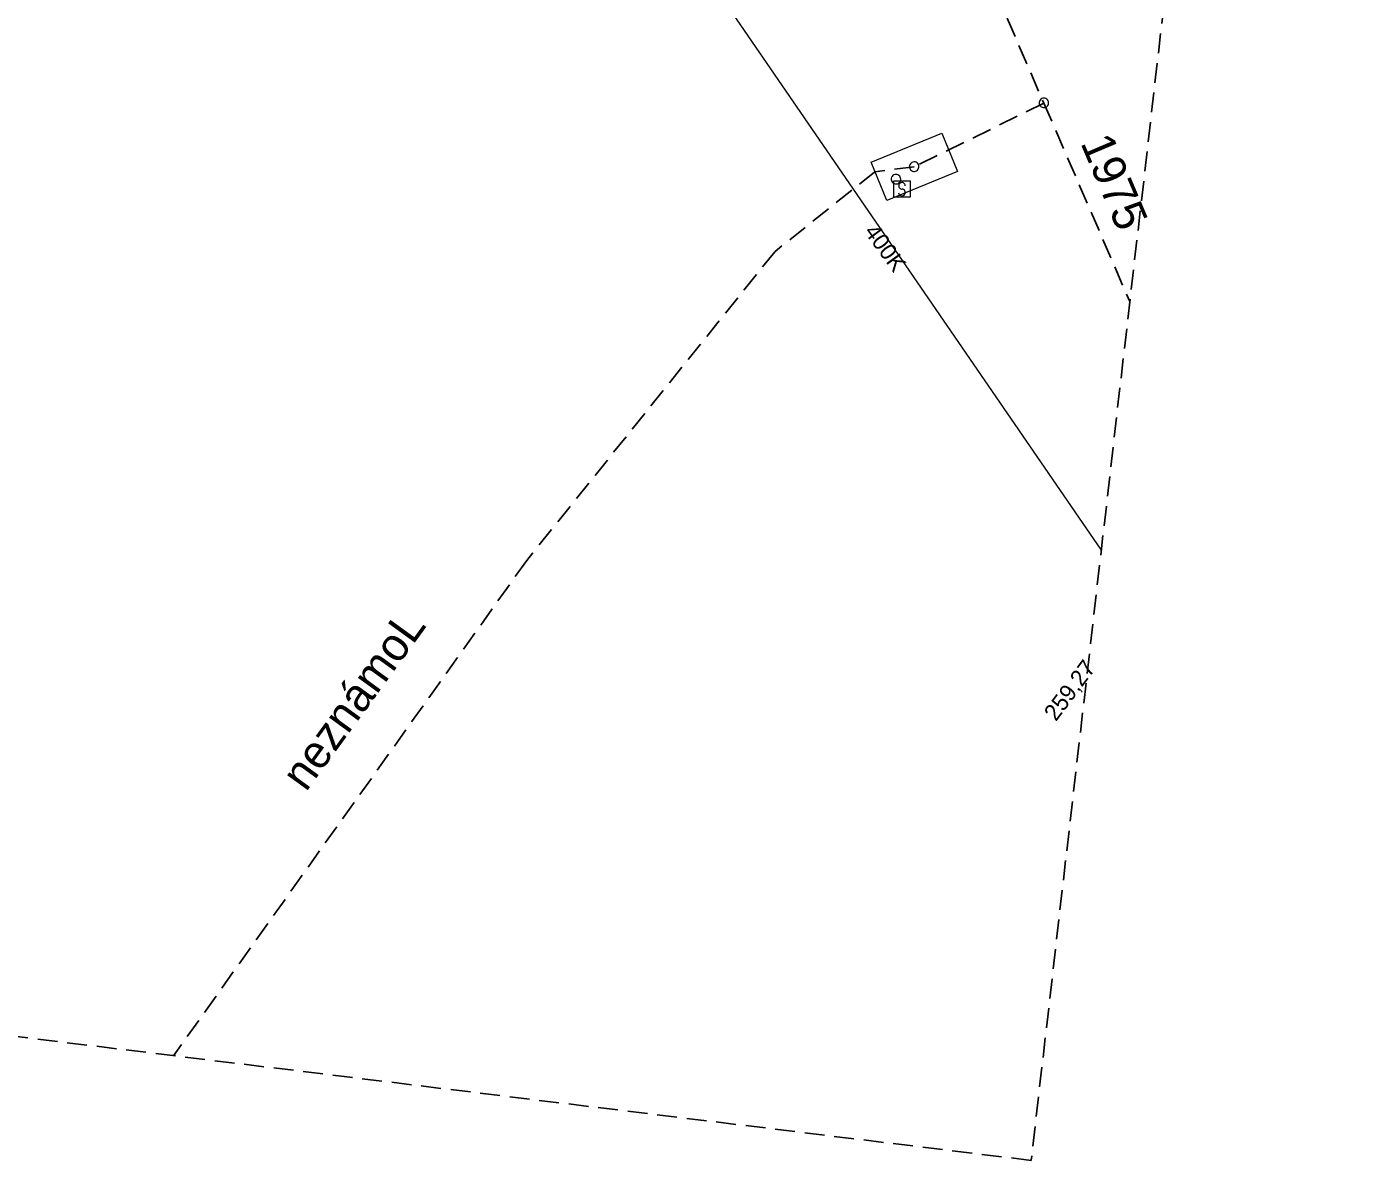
# Model space of a CAD drawing. Extents: x -743212 to -743020, y -1051380 to -1051228.
# Drawn here: x -743084.5 to -743020, y -1051380.3 to -1051325.4 of the extents above; entities that cross this region are included whole.
import ezdxf

# ---------------------------------------------------------------- set-up
doc = ezdxf.new("R2010")
doc.units = 0
doc.header["$LTSCALE"] = 0.32
doc.linetypes.add('MEDIUM_DASHED', pattern=[4.5, 3, -1.5])
for name, color, linetype, lineweight in [('1', 7, 'MEDIUM_DASHED', 25), ('20', 7, 'Continuous', 13), ('8', 7, 'Continuous', 13)]:
    doc.layers.add(name, color=color, linetype=linetype, lineweight=lineweight)

msp = doc.modelspace()

# ---------------------------------------------------------------- linework, layer by layer
at = {"layer": '1'}
msp.add_lwpolyline([(-743194.153, -1051227.724), (-743020.025, -1051242.759), (-743020.023, -1051242.759), (-743020.021, -1051242.76), (-743020.02, -1051242.761), (-743020.018, -1051242.762), (-743020.017, -1051242.764), (-743020.016, -1051242.766), (-743020.016, -1051242.768), (-743020.016, -1051242.77), (-743035.817, -1051380.315), (-743035.817, -1051380.317), (-743035.818, -1051380.318), (-743035.819, -1051380.32), (-743035.82, -1051380.321), (-743035.822, -1051380.322), (-743035.824, -1051380.323), (-743035.826, -1051380.323), (-743035.828, -1051380.323), (-743211.786, -1051358.847)], dxfattribs=at)
at = {"layer": '20'}
msp.add_line((-743053.699, -1051319.8), (-743032.423, -1051350.772), dxfattribs=at)
msp.add_line((-743053.699, -1051319.8), (-743032.423, -1051350.772), dxfattribs=at)
at = {"layer": '8', "linetype": 'MEDIUM_DASHED', "lineweight": 25}
for p, q in [((-743041.565, -1051314.439), (-743035.204, -1051329.117)), ((-743035.204, -1051329.117), (-743041.488, -1051332.205)), ((-743035.204, -1051329.117), (-743031.04, -1051338.73))]:
    msp.add_line(p, q, dxfattribs=at)
at = {"layer": '8'}
for points in [[(-743034.973, -1051329.106), (-743034.979, -1051329.054), (-743034.997, -1051329.004), (-743035.025, -1051328.96), (-743035.063, -1051328.923), (-743035.108, -1051328.896), (-743035.158, -1051328.88), (-743035.21, -1051328.875), (-743035.262, -1051328.882), (-743035.311, -1051328.901), (-743035.355, -1051328.931), (-743035.39, -1051328.97), (-743035.416, -1051329.015), (-743035.431, -1051329.066), (-743035.434, -1051329.118), (-743035.426, -1051329.17), (-743035.405, -1051329.218), (-743035.375, -1051329.261), (-743035.335, -1051329.296), (-743035.289, -1051329.32), (-743035.238, -1051329.334), (-743035.186, -1051329.336), (-743035.134, -1051329.326), (-743035.086, -1051329.304), (-743035.044, -1051329.272), (-743035.011, -1051329.232), (-743034.987, -1051329.185), (-743034.975, -1051329.134)], [(-743040.149, -1051330.58), (-743039.394, -1051332.432), (-743042.82, -1051333.83), (-743043.576, -1051331.977)], [(-743041.257, -1051332.194), (-743041.263, -1051332.142), (-743041.281, -1051332.092), (-743041.309, -1051332.048), (-743041.347, -1051332.011), (-743041.392, -1051331.984), (-743041.442, -1051331.968), (-743041.494, -1051331.963), (-743041.546, -1051331.97), (-743041.595, -1051331.989), (-743041.639, -1051332.019), (-743041.674, -1051332.058), (-743041.7, -1051332.103), (-743041.715, -1051332.154), (-743041.718, -1051332.206), (-743041.71, -1051332.258), (-743041.689, -1051332.306), (-743041.659, -1051332.349), (-743041.619, -1051332.384), (-743041.573, -1051332.408), (-743041.522, -1051332.422), (-743041.47, -1051332.424), (-743041.418, -1051332.414), (-743041.37, -1051332.392), (-743041.328, -1051332.36), (-743041.295, -1051332.32), (-743041.271, -1051332.273), (-743041.259, -1051332.222)], [(-743042.137, -1051332.8), (-743042.143, -1051332.748), (-743042.161, -1051332.698), (-743042.189, -1051332.654), (-743042.227, -1051332.617), (-743042.272, -1051332.59), (-743042.322, -1051332.574), (-743042.374, -1051332.569), (-743042.426, -1051332.576), (-743042.475, -1051332.595), (-743042.519, -1051332.625), (-743042.554, -1051332.664), (-743042.58, -1051332.709), (-743042.595, -1051332.76), (-743042.598, -1051332.812), (-743042.59, -1051332.864), (-743042.569, -1051332.912), (-743042.539, -1051332.955), (-743042.499, -1051332.99), (-743042.453, -1051333.014), (-743042.402, -1051333.028), (-743042.35, -1051333.03), (-743042.298, -1051333.02), (-743042.25, -1051332.998), (-743042.208, -1051332.966), (-743042.175, -1051332.926), (-743042.151, -1051332.879), (-743042.139, -1051332.828)], [(-743042.468, -1051332.878), (-743041.678, -1051332.878), (-743041.678, -1051333.678), (-743042.468, -1051333.678)]]:
    msp.add_lwpolyline(points, close=True, dxfattribs=at)
at = {"layer": '8', "linetype": 'MEDIUM_DASHED', "lineweight": 25}
msp.add_lwpolyline([(-743041.488, -1051332.205), (-743043.39, -1051332.44), (-743048.23, -1051336.3), (-743060.26, -1051351.27), (-743077.368, -1051375.253)], dxfattribs=at)
at = {"layer": '8'}
for points in [[(-743042.241, -1051333.461), (-743042.231, -1051333.504), (-743042.209, -1051333.543), (-743042.178, -1051333.574), (-743042.14, -1051333.595), (-743042.097, -1051333.606), (-743042.053, -1051333.604), (-743042.011, -1051333.591), (-743041.974, -1051333.567), (-743041.945, -1051333.534), (-743041.926, -1051333.494), (-743041.918, -1051333.451), (-743041.922, -1051333.407), (-743041.938, -1051333.366), (-743041.964, -1051333.331), (-743041.999, -1051333.304), (-743042.04, -1051333.287), (-743042.066, -1051333.282)], [(-743041.919, -1051333.124), (-743041.924, -1051333.081), (-743041.941, -1051333.04), (-743041.968, -1051333.006), (-743042.004, -1051332.98), (-743042.045, -1051332.965), (-743042.088, -1051332.962), (-743042.131, -1051332.97), (-743042.17, -1051332.99), (-743042.203, -1051333.019), (-743042.226, -1051333.057), (-743042.238, -1051333.099), (-743042.239, -1051333.142), (-743042.227, -1051333.185), (-743042.205, -1051333.222), (-743042.173, -1051333.253), (-743042.135, -1051333.273), (-743042.092, -1051333.282), (-743042.066, -1051333.282)]]:
    msp.add_lwpolyline(points, dxfattribs=at)

# ---------------------------------------------------------------- texts
at = {"layer": '1'}
for s, height, rotation, p in [('1975', 1.6, 293, (-743033.447, -1051331.038)), ('400K', 0.8, 306, (-743043.94, -1051335.349)), ('neznámoL', 1.6, 54, (-743070.956, -1051362.511)), ('259,27', 0.8, 53, (-743034.621, -1051359.095))]:
    msp.add_text(s, height=height, rotation=rotation, dxfattribs=at).set_placement(p)

doc.saveas('drawing.dxf')
